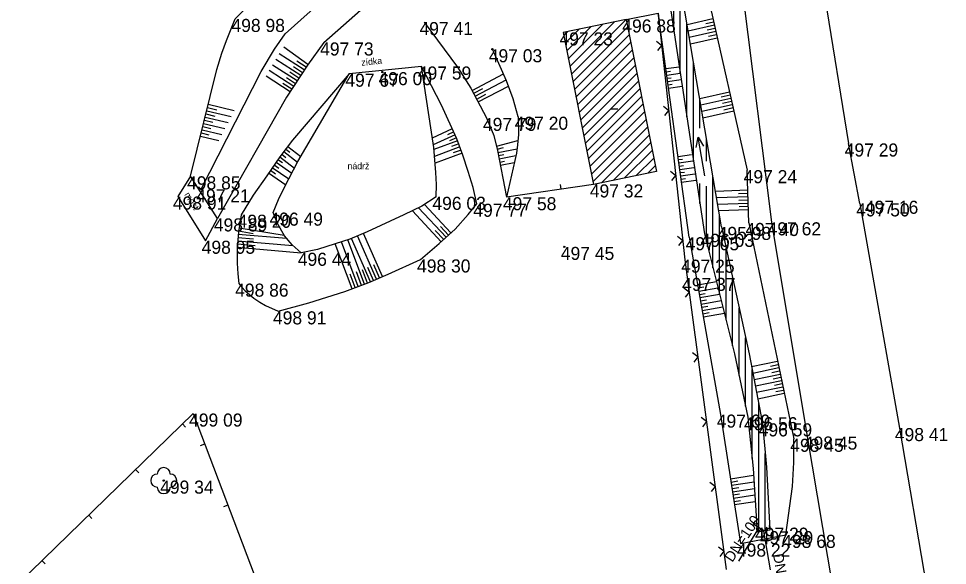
# Model space of a CAD drawing. Extents: x -554123 to -553118, y -1076825 to -1073672.
# Drawn here: x -553501.5 to -553430.4, y -1076768 to -1076726.2 of the extents above; entities that cross this region are included whole.
import ezdxf

# ---------------------------------------------------------------- set-up
doc = ezdxf.new("R2010")
doc.units = 0
for name, color, linetype in [('1', 7, 'Continuous'), ('12', 7, 'Continuous'), ('14', 7, 'Continuous'), ('17', 7, 'Continuous'), ('18', 7, 'Continuous'), ('26', 7, 'Continuous'), ('27', 7, 'Continuous'), ('28', 7, 'Continuous'), ('32', 7, 'Continuous'), ('34', 7, 'Continuous'), ('40', 7, 'Continuous'), ('47', 7, 'Continuous'), ('49', 7, 'Continuous'), ('52', 7, 'Continuous'), ('6', 7, 'Continuous')]:
    doc.layers.add(name, color=color, linetype=linetype)

# ---------------------------------------------------------------- blocks, each defined once
blk = doc.blocks.new('POINT_DISPLAY')
blk.add_line((0, 0), (0, 0))
blk = doc.blocks.new('T')
at = {"layer": '6'}
blk.add_circle((0, 0), 0.05, dxfattribs=at)
blk = doc.blocks.new('VOTOK')
at = {"layer": '28'}
for p, q in [((-3.001, 0), (0, 0)), ((-0.75, 0.282), (0, 0)), ((0, 0), (-0.75, -0.28))]:
    blk.add_line(p, q, dxfattribs=at)
blk = doc.blocks.new('JS800')
at = {"layer": '49'}
blk.add_text('DN=800', height=0.8, rotation=359.99988, dxfattribs=at).set_placement((0, 0))
blk = doc.blocks.new('STL')
at = {"layer": '34'}
blk.add_circle((0, 0), 0.05, dxfattribs=at)
for centre, start, end in [((0, 0.5), 0, 180), ((-0.5, 0), 90, 270), ((0.5, 0), 270, 90), ((0, -0.5), 180, 0)]:
    blk.add_arc(centre, 0.5, start, end, dxfattribs=at)
blk = doc.blocks.new('VYUST')
at = {"layer": '40'}
for p, q in [((-0.35, 0.501), (0, 0.5)), ((0, 0.5), (0, -0.5)), ((0, 0), (3, 0)), ((-0.35, -0.5), (0, -0.5))]:
    blk.add_line(p, q, dxfattribs=at)
blk = doc.blocks.new('BN')
at = {"layer": '47'}
blk.add_line((-0.25, 0), (0.25, 0), dxfattribs=at)
blk = doc.blocks.new('JS100')
at = {"layer": '49'}
blk.add_text('DN=100', height=0.8, rotation=359.99998, dxfattribs=at).set_placement((0, 0))

msp = doc.modelspace()

# ---------------------------------------------------------------- linework, layer by layer
at = {"layer": '12'}
for p, q in [((-553455.03, -1076726.24), (-553452.578, -1076725.751)), ((-553452.578, -1076725.751), (-553450.54, -1076744.62)), ((-553452.31, -1076728.237), (-553452.7, -1076727.923)), ((-553452.31, -1076728.237), (-553452.623, -1076728.627)), ((-553451.773, -1076733.208), (-553452.163, -1076732.894)), ((-553451.773, -1076733.208), (-553452.087, -1076733.598)), ((-553451.236, -1076738.179), (-553451.626, -1076737.865)), ((-553451.236, -1076738.179), (-553451.55, -1076738.569)), ((-553457.53, -1076738.86), (-553464.18, -1076739.84)), ((-553460.003, -1076739.224), (-553460.054, -1076738.878)), ((-553450.699, -1076743.15), (-553451.089, -1076742.836)), ((-553450.699, -1076743.15), (-553451.013, -1076743.54)), ((-553450.54, -1076744.62), (-553447.37, -1076768.32)), ((-553450.209, -1076747.098), (-553450.606, -1076746.794)), ((-553450.209, -1076747.098), (-553450.513, -1076747.496)), ((-553449.546, -1076752.054), (-553449.943, -1076751.75)), ((-553449.546, -1076752.054), (-553449.85, -1076752.452)), ((-553501.52, -1076769.39), (-553488.17, -1076756.39)), ((-553488.17, -1076756.39), (-553482.04, -1076772.53)), ((-553488.982, -1076757.181), (-553488.738, -1076757.432)), ((-553448.883, -1076757.01), (-553449.281, -1076756.706)), ((-553448.883, -1076757.01), (-553449.187, -1076757.407)), ((-553487.282, -1076758.727), (-553487.61, -1076758.851)), ((-553492.565, -1076760.669), (-553492.32, -1076760.92)), ((-553448.22, -1076761.966), (-553448.618, -1076761.662)), ((-553448.22, -1076761.966), (-553448.524, -1076762.363)), ((-553485.507, -1076763.401), (-553485.834, -1076763.526)), ((-553496.147, -1076764.158), (-553495.903, -1076764.408)), ((-553447.557, -1076766.921), (-553447.955, -1076766.617)), ((-553447.557, -1076766.921), (-553447.861, -1076767.319)), ((-553499.729, -1076767.646), (-553499.485, -1076767.897))]:
    msp.add_line(p, q, dxfattribs=at)
at = {"layer": '14'}
for p, q in [((-553455.03, -1076726.24), (-553459.85, -1076727.23)), ((-553455.03, -1076726.24), (-553452.71, -1076737.87)), ((-553459.85, -1076727.23), (-553457.53, -1076738.86)), ((-553452.71, -1076737.87), (-553457.53, -1076738.86))]:
    msp.add_line(p, q, dxfattribs=at)
at = {"layer": '17'}
for p, q in [((-553440.39, -1076721), (-553438.01, -1076735.73)), ((-553446.23, -1076723.25), (-553443.91, -1076741.76)), ((-553437.14, -1076740.31), (-553438.01, -1076735.73)), ((-553437.14, -1076740.31), (-553434.09, -1076757.5)), ((-553443.91, -1076741.76), (-553441.16, -1076758.15)), ((-553434.09, -1076757.5), (-553431.22, -1076774.44)), ((-553441.16, -1076758.15), (-553438.18, -1076775.84))]:
    msp.add_line(p, q, dxfattribs=at)
at = {"layer": '18'}
for p, q in [((-553470.68, -1076729.84), (-553476.23, -1076730.39)), ((-553488.35, -1076738.24), (-553489.32, -1076739.79)), ((-553486.29, -1076741.46), (-553488.35, -1076738.24)), ((-553489.32, -1076739.79), (-553487.22, -1076743.17)), ((-553487.22, -1076743.17), (-553486.29, -1076741.46))]:
    msp.add_line(p, q, dxfattribs=at)
at = {"layer": '26'}
for p, q in [((-553448.377, -1076726.199), (-553450.355, -1076726.645)), ((-553448.322, -1076726.443), (-553448.919, -1076726.577)), ((-553448.267, -1076726.687), (-553450.271, -1076727.138)), ((-553448.157, -1076727.174), (-553450.187, -1076727.631)), ((-553448.212, -1076726.93), (-553448.817, -1076727.066)), ((-553448.047, -1076727.662), (-553450.103, -1076728.125)), ((-553448.102, -1076727.418), (-553448.715, -1076727.556)), ((-553479.378, -1076729.688), (-553481.223, -1076728.367)), ((-553479.924, -1076730.526), (-553481.822, -1076729.297)), ((-553479.652, -1076730.106), (-553481.567, -1076728.867)), ((-553479.516, -1076729.896), (-553480.216, -1076729.443)), ((-553480.467, -1076731.365), (-553482.333, -1076730.157)), ((-553480.196, -1076730.945), (-553482.077, -1076729.727)), ((-553479.788, -1076730.316), (-553480.486, -1076729.864)), ((-553451.986, -1076730.003), (-553450.952, -1076729.859)), ((-553451.951, -1076730.251), (-553451.64, -1076730.208)), ((-553480.739, -1076731.785), (-553482.582, -1076730.592)), ((-553480.331, -1076731.155), (-553481.019, -1076730.71)), ((-553480.06, -1076730.736), (-553480.753, -1076730.287)), ((-553466.806, -1076731.665), (-553464.418, -1076730.411)), ((-553466.573, -1076732.107), (-553464.214, -1076730.868)), ((-553451.917, -1076730.499), (-553450.877, -1076730.354)), ((-553451.882, -1076730.746), (-553451.57, -1076730.703)), ((-553451.848, -1076730.994), (-553450.803, -1076730.848)), ((-553480.603, -1076731.575), (-553481.286, -1076731.133)), ((-553466.69, -1076731.886), (-553465.978, -1076731.512)), ((-553466.341, -1076732.55), (-553464.031, -1076731.337)), ((-553451.813, -1076731.241), (-553451.499, -1076731.197)), ((-553451.779, -1076731.489), (-553450.729, -1076731.343)), ((-553466.457, -1076732.329), (-553465.756, -1076731.961)), ((-553447.116, -1076731.795), (-553449.394, -1076732.308)), ((-553447.006, -1076732.282), (-553449.31, -1076732.801)), ((-553447.061, -1076732.038), (-553447.749, -1076732.193)), ((-553487.064, -1076732.978), (-553486.342, -1076733.155)), ((-553487.005, -1076732.735), (-553485.023, -1076733.22)), ((-553446.896, -1076732.77), (-553449.226, -1076733.295)), ((-553446.951, -1076732.526), (-553447.646, -1076732.683)), ((-553446.842, -1076733.014), (-553447.544, -1076733.172)), ((-553487.242, -1076733.706), (-553485.489, -1076734.135)), ((-553487.183, -1076733.464), (-553486.495, -1076733.632)), ((-553487.124, -1076733.221), (-553485.256, -1076733.678)), ((-553446.787, -1076733.258), (-553449.142, -1076733.789)), ((-553487.42, -1076734.435), (-553486.8, -1076734.586)), ((-553487.361, -1076734.192), (-553485.723, -1076734.593)), ((-553487.302, -1076733.949), (-553486.648, -1076734.109)), ((-553487.598, -1076735.164), (-553486.189, -1076735.509)), ((-553487.539, -1076734.921), (-553486.954, -1076735.064)), ((-553487.48, -1076734.678), (-553485.956, -1076735.051)), ((-553468.326, -1076734.614), (-553469.856, -1076735.317)), ((-553468.117, -1076735.068), (-553469.779, -1076735.832)), ((-553468.221, -1076734.841), (-553468.7, -1076735.061)), ((-553467.92, -1076735.527), (-553469.734, -1076736.199)), ((-553468.013, -1076735.295), (-553468.532, -1076735.534)), ((-553467.833, -1076735.762), (-553468.397, -1076735.971)), ((-553464.951, -1076735.926), (-553463.303, -1076735.503)), ((-553481.382, -1076736.55), (-553481.057, -1076736.801)), ((-553481.229, -1076736.352), (-553480.181, -1076737.16)), ((-553481.076, -1076736.154), (-553480.771, -1076736.39)), ((-553480.924, -1076735.956), (-553479.93, -1076736.723)), ((-553467.746, -1076735.996), (-553469.689, -1076736.716)), ((-553467.573, -1076736.465), (-553469.645, -1076737.233)), ((-553467.66, -1076736.23), (-553468.262, -1076736.454)), ((-553464.889, -1076736.168), (-553464.418, -1076736.047)), ((-553464.836, -1076736.412), (-553463.369, -1076736.131)), ((-553464.789, -1076736.658), (-553464.375, -1076736.579)), ((-553451.051, -1076736.72), (-553450.01, -1076736.575)), ((-553481.819, -1076737.159), (-553480.613, -1076737.992)), ((-553481.677, -1076736.954), (-553481.323, -1076737.198)), ((-553481.534, -1076736.748), (-553480.415, -1076737.611)), ((-553464.742, -1076736.903), (-553463.462, -1076736.658)), ((-553464.695, -1076737.149), (-553464.343, -1076737.082)), ((-553464.648, -1076737.394), (-553463.582, -1076737.19)), ((-553451.016, -1076736.968), (-553450.702, -1076736.924)), ((-553450.982, -1076737.215), (-553449.931, -1076737.069)), ((-553482.387, -1076737.982), (-553481.077, -1076738.886)), ((-553482.245, -1076737.776), (-553481.86, -1076738.042)), ((-553482.103, -1076737.571), (-553480.845, -1076738.439)), ((-553481.961, -1076737.365), (-553481.591, -1076737.62)), ((-553450.947, -1076737.463), (-553450.63, -1076737.419)), ((-553450.913, -1076737.711), (-553449.851, -1076737.563)), ((-553450.878, -1076737.958), (-553450.558, -1076737.913)), ((-553450.844, -1076738.206), (-553449.771, -1076738.057)), ((-553450.809, -1076738.453), (-553450.486, -1076738.408)), ((-553450.775, -1076738.701), (-553449.691, -1076738.55)), ((-553445.716, -1076739.315), (-553448.165, -1076739.4)), ((-553445.699, -1076739.815), (-553448.085, -1076739.898)), ((-553445.708, -1076739.565), (-553446.433, -1076739.59)), ((-553445.69, -1076740.064), (-553446.397, -1076740.089)), ((-553469.166, -1076743.25), (-553471.385, -1076740.872)), ((-553468.8, -1076742.909), (-553470.914, -1076740.644)), ((-553468.435, -1076742.568), (-553470.464, -1076740.394)), ((-553445.682, -1076740.314), (-553448.006, -1076740.394)), ((-553445.665, -1076740.814), (-553447.926, -1076740.892)), ((-553445.673, -1076740.564), (-553446.361, -1076740.588)), ((-553484.645, -1076742.175), (-553481.205, -1076742.744)), ((-553468.618, -1076742.738), (-553469.236, -1076742.076)), ((-553484.732, -1076742.919), (-553483.548, -1076743.02)), ((-553484.711, -1076742.67), (-553481.012, -1076742.986)), ((-553484.685, -1076742.421), (-553483.571, -1076742.605)), ((-553474.587, -1076746.314), (-553476.042, -1076742.991)), ((-553474.129, -1076746.114), (-553475.58, -1076742.8)), ((-553473.671, -1076745.913), (-553475.118, -1076742.608)), ((-553468.983, -1076743.08), (-553469.633, -1076742.383)), ((-553484.796, -1076743.666), (-553479.896, -1076744.084)), ((-553484.775, -1076743.417), (-553483.408, -1076743.534)), ((-553484.754, -1076743.168), (-553480.54, -1076743.528)), ((-553475.988, -1076746.849), (-553477.284, -1076743.405)), ((-553475.52, -1076746.673), (-553476.808, -1076743.25)), ((-553475.052, -1076746.497), (-553476.332, -1076743.096)), ((-553473.9, -1076746.013), (-553474.335, -1076745.021)), ((-553475.754, -1076746.761), (-553476.142, -1076745.731)), ((-553475.286, -1076746.585), (-553475.671, -1076745.561)), ((-553474.818, -1076746.409), (-553475.201, -1076745.39)), ((-553474.358, -1076746.214), (-553474.794, -1076745.218)), ((-553449.547, -1076746.538), (-553448.116, -1076746.285)), ((-553449.503, -1076746.784), (-553449.069, -1076746.707)), ((-553449.459, -1076747.031), (-553447.994, -1076746.772)), ((-553449.416, -1076747.277), (-553448.971, -1076747.198)), ((-553449.372, -1076747.523), (-553447.872, -1076747.258)), ((-553449.329, -1076747.769), (-553448.873, -1076747.688)), ((-553449.285, -1076748.015), (-553447.75, -1076747.743)), ((-553449.242, -1076748.261), (-553448.776, -1076748.179)), ((-553449.198, -1076748.508), (-553447.628, -1076748.23)), ((-553449.155, -1076748.754), (-553448.678, -1076748.67)), ((-553449.111, -1076749), (-553447.506, -1076748.716)), ((-553443.427, -1076752.413), (-553445.416, -1076752.826)), ((-553443.325, -1076752.903), (-553445.32, -1076753.318)), ((-553443.376, -1076752.658), (-553443.974, -1076752.782)), ((-553443.224, -1076753.392), (-553445.225, -1076753.808)), ((-553443.275, -1076753.148), (-553443.874, -1076753.272)), ((-553443.173, -1076753.637), (-553443.774, -1076753.762)), ((-553443.122, -1076753.882), (-553445.13, -1076754.299)), ((-553443.02, -1076754.371), (-553445.035, -1076754.79)), ((-553443.071, -1076754.127), (-553443.675, -1076754.252)), ((-553442.919, -1076754.861), (-553444.94, -1076755.281)), ((-553442.969, -1076754.616), (-553443.575, -1076754.742)), ((-553447.033, -1076761.383), (-553445.265, -1076761.111)), ((-553446.995, -1076761.63), (-553446.471, -1076761.55)), ((-553446.957, -1076761.877), (-553445.233, -1076761.612)), ((-553446.919, -1076762.125), (-553446.409, -1076762.046)), ((-553446.881, -1076762.372), (-553445.201, -1076762.113)), ((-553446.843, -1076762.619), (-553446.346, -1076762.542)), ((-553446.805, -1076762.866), (-553445.17, -1076762.614)), ((-553446.767, -1076763.113), (-553446.283, -1076763.039)), ((-553446.729, -1076763.36), (-553445.138, -1076763.115))]:
    msp.add_line(p, q, dxfattribs=at)
at = {"layer": '27'}
for p, q in [((-553478.17, -1076728), (-553473.83, -1076724.16)), ((-553448.78, -1076724.41), (-553445.77, -1076737.77)), ((-553450.19, -1076742.9), (-553452.578, -1076725.751)), ((-553445.63, -1076741.81), (-553445.77, -1076737.77)), ((-553445.63, -1076741.81), (-553442.2, -1076758.32)), ((-553450.19, -1076742.9), (-553447.79, -1076756.47)), ((-553447.79, -1076756.47), (-553446.27, -1076766.34)), ((-553446.27, -1076766.34), (-553442.79, -1076765.67))]:
    msp.add_line(p, q, dxfattribs=at)
for points in [[(-553484.94, -1076726.2), (-553483.576, -1076724.851), (-553482.505, -1076723.954), (-553479.08, -1076721.06)], [(-553488.35, -1076738.24), (-553486.356, -1076730.078), (-553485.958, -1076728.811), (-553485.603, -1076727.849), (-553484.94, -1076726.2)], [(-553470.47, -1076726.44), (-553467.928, -1076729.9), (-553466.897, -1076731.491), (-553465.7, -1076733.77)], [(-553478.17, -1076728), (-553479.414, -1076729.738), (-553481.007, -1076732.199), (-553486.29, -1076741.46)], [(-553463.28, -1076733.68), (-553463.656, -1076732.316), (-553464.186, -1076730.932), (-553465.26, -1076728.52)], [(-553466.45, -1076740.34), (-553466.742, -1076739.092), (-553467.118, -1076737.87), (-553467.516, -1076736.618), (-553467.98, -1076735.366), (-553469.165, -1076732.788), (-553470.68, -1076729.84)], [(-553469.56, -1076739.81), (-553469.524, -1076738.87), (-553469.583, -1076737.957), (-553469.747, -1076736.043), (-553470.68, -1076729.84)], [(-553476.23, -1076730.39), (-553480.559, -1076735.483), (-553481.536, -1076736.75), (-553482.533, -1076738.194), (-553483.569, -1076739.696), (-553484.48, -1076741.18)], [(-553482.03, -1076741.02), (-553481.639, -1076740.02), (-553481.168, -1076739.062), (-553480.152, -1076737.103), (-553476.23, -1076730.39)], [(-553465.7, -1076733.77), (-553465.159, -1076735.115), (-553464.864, -1076736.264), (-553464.18, -1076739.84)], [(-553463.28, -1076733.68), (-553463.273, -1076735.056), (-553463.325, -1076735.837), (-553463.42, -1076736.47), (-553464.18, -1076739.84)], [(-553469.56, -1076739.81), (-553470.658, -1076740.52), (-553472.028, -1076741.183), (-553474.844, -1076742.495), (-553476.16, -1076743.04), (-553477.294, -1076743.408), (-553478.649, -1076743.835), (-553479.89, -1076744.09)], [(-553470.75, -1076744.6), (-553469.32, -1076743.394), (-553468.12, -1076742.274), (-553467.111, -1076741.169), (-553466.45, -1076740.34)], [(-553484.48, -1076741.18), (-553484.695, -1076742.48), (-553484.802, -1076743.733), (-553484.784, -1076744.896), (-553484.739, -1076745.713), (-553484.66, -1076746.45)], [(-553479.89, -1076744.09), (-553480.593, -1076743.482), (-553481.178, -1076742.79), (-553481.713, -1076741.861), (-553482.03, -1076741.02)], [(-553481.66, -1076748.57), (-553479.301, -1076747.931), (-553476.553, -1076747.062), (-553474.712, -1076746.369), (-553473.232, -1076745.721), (-553470.75, -1076744.6)], [(-553484.66, -1076746.45), (-553484.423, -1076746.73), (-553484.169, -1076747.002), (-553483.506, -1076747.563), (-553483.053, -1076747.871), (-553482.622, -1076748.122), (-553481.66, -1076748.57)], [(-553442.79, -1076765.67), (-553442.296, -1076761.98), (-553442.191, -1076760.133), (-553442.2, -1076758.32)]]:
    msp.add_lwpolyline(points, dxfattribs=at)
at = {"layer": '28'}
for p, q in [((-553481.106, -1076727.336), (-553468.69, -1076716.15)), ((-553451.877, -1076723.705), (-553449.03, -1076742.64)), ((-553447.73, -1076742.11), (-553450.902, -1076723.42))]:
    msp.add_line(p, q, dxfattribs=at)
for points in [[(-553487.54, -1076739.23), (-553482.947, -1076730.215), (-553481.933, -1076728.507), (-553481.106, -1076727.336)], [(-553447.73, -1076742.11), (-553445.611, -1076751.817), (-553444.58, -1076757.14)], [(-553449.03, -1076742.64), (-553446.728, -1076751.817), (-553445.7, -1076756.67)], [(-553445.7, -1076756.67), (-553445.297, -1076760.603), (-553444.991, -1076765.436)], [(-553444.58, -1076757.14), (-553444.285, -1076760.498), (-553444.032, -1076765.262)]]:
    msp.add_lwpolyline(points, dxfattribs=at)
at = {"layer": '32'}
for p, q in [((-553451.377, -1076727.03), (-553451.377, -1076723.559)), ((-553450.877, -1076730.356), (-553450.877, -1076723.567)), ((-553459.448, -1076729.244), (-553456.81, -1076726.606)), ((-553459.331, -1076729.834), (-553455.92, -1076726.423)), ((-553459.213, -1076730.423), (-553455.03, -1076726.24)), ((-553450.377, -1076733.681), (-553450.377, -1076726.513)), ((-553459.801, -1076727.475), (-553459.479, -1076727.154)), ((-553459.683, -1076728.065), (-553458.59, -1076726.971)), ((-553459.566, -1076728.655), (-553457.7, -1076726.788)), ((-553459.095, -1076731.013), (-553454.912, -1076726.83)), ((-553458.978, -1076731.602), (-553454.795, -1076727.419)), ((-553458.86, -1076732.192), (-553454.677, -1076728.009)), ((-553458.743, -1076732.781), (-553454.56, -1076728.598)), ((-553458.625, -1076733.371), (-553454.442, -1076729.188)), ((-553449.877, -1076737.007), (-553449.877, -1076729.459)), ((-553458.507, -1076733.96), (-553454.324, -1076729.777)), ((-553458.39, -1076734.55), (-553454.207, -1076730.367)), ((-553458.272, -1076735.139), (-553454.089, -1076730.956)), ((-553458.155, -1076735.729), (-553453.972, -1076731.546)), ((-553458.037, -1076736.318), (-553453.854, -1076732.135)), ((-553457.919, -1076736.908), (-553453.736, -1076732.725)), ((-553449.377, -1076734.57), (-553449.377, -1076732.406)), ((-553457.802, -1076737.497), (-553453.619, -1076733.314)), ((-553457.684, -1076738.087), (-553453.501, -1076733.904)), ((-553457.567, -1076738.676), (-553453.384, -1076734.493)), ((-553456.918, -1076738.734), (-553453.266, -1076735.083)), ((-553456.028, -1076738.551), (-553453.148, -1076735.672)), ((-553448.877, -1076737.091), (-553448.877, -1076735.352)), ((-553455.138, -1076738.369), (-553453.031, -1076736.262)), ((-553454.248, -1076738.186), (-553452.913, -1076736.851)), ((-553453.358, -1076738.003), (-553452.796, -1076737.441)), ((-553448.377, -1076745.243), (-553448.377, -1076738.298)), ((-553449.377, -1076740.332), (-553449.377, -1076738.8)), ((-553448.877, -1076743.25), (-553448.877, -1076739.006)), ((-553447.877, -1076747.236), (-553447.877, -1076741.244)), ((-553447.377, -1076749.23), (-553447.377, -1076743.727)), ((-553446.877, -1076751.223), (-553446.877, -1076746.018)), ((-553446.377, -1076753.474), (-553446.377, -1076748.308)), ((-553445.877, -1076755.834), (-553445.877, -1076750.598)), ((-553445.377, -1076759.822), (-553445.377, -1076753.025)), ((-553444.877, -1076765.415), (-553444.877, -1076755.607)), ((-553444.377, -1076765.325), (-553444.377, -1076759.451))]:
    msp.add_line(p, q, dxfattribs=at)

# ---------------------------------------------------------------- block references
at = {"layer": '1'}
for p in [(-553484.94, -1076726.2), (-553470.47, -1076726.44), (-553455.03, -1076726.24), (-553459.85, -1076727.23), (-553478.17, -1076728), (-553465.26, -1076728.52), (-553470.68, -1076729.84), (-553476.23, -1076730.39), (-553473.68, -1076730.27), (-553465.7, -1076733.77), (-553463.28, -1076733.68), (-553438.01, -1076735.73), (-553445.77, -1076737.77), (-553488.35, -1076738.24), (-553487.54, -1076739.23), (-553457.53, -1076738.86), (-553489.32, -1076739.79), (-553469.56, -1076739.81), (-553464.18, -1076739.84), (-553436.36, -1076740.11), (-553466.45, -1076740.34), (-553437.14, -1076740.31), (-553486.29, -1076741.46), (-553484.48, -1076741.18), (-553482.03, -1076741.02), (-553447.73, -1076742.11), (-553445.63, -1076741.81), (-553443.91, -1076741.76), (-553450.19, -1076742.9), (-553449.03, -1076742.64), (-553487.22, -1076743.17), (-553459.76, -1076743.64), (-553479.89, -1076744.09), (-553470.75, -1076744.6), (-553450.54, -1076744.62), (-553484.66, -1076746.45), (-553450.47, -1076746.01), (-553481.66, -1076748.57), (-553488.17, -1076756.39), (-553447.79, -1076756.47), (-553445.7, -1076756.67), (-553444.58, -1076757.14), (-553434.09, -1076757.5), (-553442.2, -1076758.32), (-553441.16, -1076758.15), (-553490.41, -1076761.52), (-553444.87, -1076765.12), (-553444.51, -1076765.39), (-553442.79, -1076765.67), (-553446.27, -1076766.34)]:
    msp.add_blockref('POINT_DISPLAY', p, dxfattribs=at)
at = {"layer": '28', "xscale": 1.0000004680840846, "yscale": 1.0000004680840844, "rotation": 99.55474033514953}
msp.add_blockref('VOTOK', (-553449.503, -1076735.25), dxfattribs=at)
at = {"layer": '32'}
msp.add_blockref('POINT_DISPLAY', (-553455.03, -1076726.24), dxfattribs=at)
at = {"layer": '34'}
msp.add_blockref('STL', (-553490.41, -1076761.52), dxfattribs=at)
at = {"layer": '40'}
for p, xscale, yscale, rotation in [((-553444.87, -1076765.12), 1.0000002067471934, 1.000000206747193, -121.33662987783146), ((-553444.51, -1076765.39), 1.000000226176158, 1.000000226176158, -80.38924721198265)]:
    msp.add_blockref('VYUST', p, dxfattribs=dict(at, xscale=xscale, yscale=yscale, rotation=rotation))
at = {"layer": '47'}
msp.add_blockref('BN', (-553455.92, -1076733.072), dxfattribs=at)
at = {"layer": '49'}
for name, p, xscale, yscale, rotation in [('JS100', (-553446.899, -1076767.82), 1.0000008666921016, 1.0000008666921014, 56.38104481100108), ('JS800', (-553443.788, -1076767.17), 0.9999985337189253, 0.9999985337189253, -80.2438855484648)]:
    msp.add_blockref(name, p, dxfattribs=dict(at, xscale=xscale, yscale=yscale, rotation=rotation))
at = {"layer": '6'}
for p in [(-553465.26, -1076728.52), (-553473.68, -1076730.27), (-553487.54, -1076739.23), (-553459.76, -1076743.64)]:
    msp.add_blockref('T', p, dxfattribs=at)

# ---------------------------------------------------------------- texts
at = {"layer": '52'}
for s, rotation, p in [('zídka', 5.65948, (-553475.27, -1076729.786)), ('most', 301.85276, (-553488.86, -1076739.645))]:
    msp.add_text(s, height=0.5, rotation=rotation, dxfattribs=at).set_placement(p)
msp.add_text('nádrž', height=0.5, dxfattribs=at).set_placement((-553476.344, -1076737.702))
at = {"layer": '6'}
for s, p in [('498 98 ', (-553485.226, -1076727.2)), ('497 41 ', (-553470.837, -1076727.44)), ('496 88 ', (-553455.316, -1076727.24)), ('497 23 ', (-553460.122, -1076728.23)), ('497 73 ', (-553478.44, -1076729)), ('497 03 ', (-553465.534, -1076729.52)), ('497 59 ', (-553470.964, -1076730.84)), ('497 67 ', (-553476.512, -1076731.39)), ('496 00 ', (-553473.97, -1076731.27)), ('497 79 ', (-553465.982, -1076734.77)), ('497 20 ', (-553463.554, -1076734.68)), ('497 29 ', (-553438.294, -1076736.73)), ('497 24 ', (-553446.03, -1076738.77)), ('498 85 ', (-553488.624, -1076739.24)), ('497 21 ', (-553487.919, -1076740.23)), ('497 32 ', (-553457.802, -1076739.86)), ('498 91 ', (-553489.713, -1076740.79)), ('496 03 ', (-553469.848, -1076740.81)), ('497 58 ', (-553464.452, -1076740.84)), ('497 16 ', (-553436.753, -1076741.11)), ('497 77 ', (-553466.718, -1076741.34)), ('497 50 ', (-553437.414, -1076741.31)), ('498 89 ', (-553486.576, -1076742.46)), ('498 20 ', (-553484.756, -1076742.18)), ('496 49 ', (-553482.316, -1076742.02)), ('495 98 ', (-553448.016, -1076743.11)), ('497 40 ', (-553445.892, -1076742.81)), ('497 62 ', (-553444.194, -1076742.76)), ('497 05 ', (-553450.464, -1076743.9)), ('496 03 ', (-553449.318, -1076743.64)), ('498 95 ', (-553487.506, -1076744.17)), ('497 45 ', (-553460.02, -1076744.64)), ('496 44 ', (-553480.152, -1076745.09)), ('498 30 ', (-553471.026, -1076745.6)), ('497 25 ', (-553450.812, -1076745.62)), ('498 86 ', (-553484.946, -1076747.45)), ('497 37 ', (-553450.74, -1076747.01)), ('498 91 ', (-553482.053, -1076749.57)), ('499 09 ', (-553488.47, -1076757.39)), ('497 69 ', (-553448.086, -1076757.47)), ('496 56 ', (-553445.998, -1076757.67)), ('496 59 ', (-553444.878, -1076758.14)), ('498 41 ', (-553434.459, -1076758.5)), ('498 45 ', (-553442.462, -1076759.32)), ('498 45 ', (-553441.422, -1076759.15)), ('499 34 ', (-553490.684, -1076762.52)), ('497 29 ', (-553445.154, -1076766.12)), ('497 29 ', (-553444.794, -1076766.39)), ('498 68 ', (-553443.076, -1076766.67)), ('498 22 ', (-553446.544, -1076767.34))]:
    msp.add_text(s, height=1, dxfattribs=at).set_placement(p)

doc.saveas('drawing.dxf')
